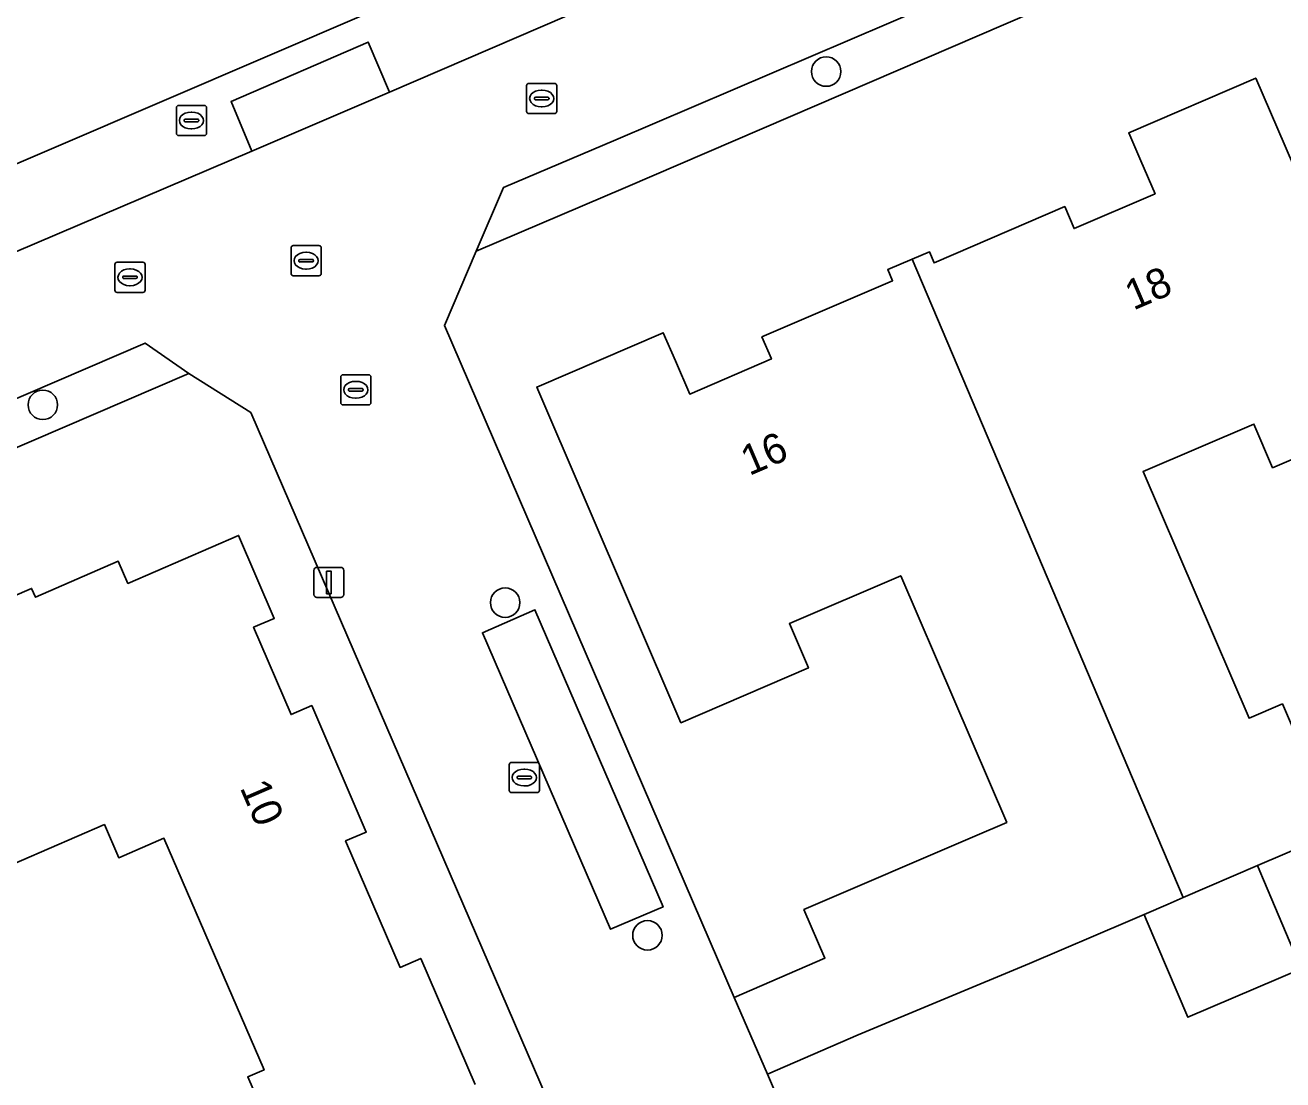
# Model space of a CAD drawing. Extents: x 157767 to 159172, y 387839 to 389425.
# Drawn here: x 158126.83 to 158168.55, y 388760.66 to 388795.64 of the extents above; entities that cross this region are included whole.
import ezdxf

# ---------------------------------------------------------------- set-up
doc = ezdxf.new("R2010")
doc.units = 0
for name, color, linetype in [('IMGEO_Boom', 7, 'Continuous'), ('IMGEO_Brandkraan', 7, 'Continuous'), ('IMGEO_Erf', 7, 'Continuous'), ('IMGEO_Kolk', 7, 'Continuous'), ('IMGEO_Lichtmast', 7, 'Continuous'), ('IMGEO_Pand', 7, 'Continuous'), ('IMGEO_Pand_nummerreeks', 7, 'Continuous'), ('IMGEO_Parkeervlak_open', 7, 'Continuous'), ('IMGEO_Rijbaan_lokaal_open', 7, 'Continuous'), ('IMGEO_Rioolput', 7, 'Continuous'), ('IMGEO_Voetpad_open', 7, 'Continuous')]:
    doc.layers.add(name, color=color, linetype=linetype)

msp = doc.modelspace()

# ---------------------------------------------------------------- linework, layer by layer
at = {"layer": 'IMGEO_Boom'}
for centre in [(158153.405, 388794.103), (158127.417, 388783.049), (158142.755, 388776.488), (158147.475, 388765.452)]:
    msp.add_circle(centre, 0.489, dxfattribs=at)
at = {"layer": 'IMGEO_Brandkraan'}
for p, q in [((158131.848, 388792.054), (158131.848, 388792.906)), ((158131.923, 388792.98), (158132.775, 388792.98)), ((158132.336, 388792.76), (158132.361, 388792.76)), ((158132.849, 388792.906), (158132.849, 388792.054)), ((158132.107, 388792.474), (158132.107, 388792.486)), ((158132.545, 388792.437), (158132.147, 388792.437)), ((158132.15, 388792.523), (158132.548, 388792.523)), ((158132.591, 388792.486), (158132.591, 388792.474)), ((158132.775, 388791.98), (158131.923, 388791.98)), ((158132.359, 388792.2), (158132.334, 388792.2))]:
    msp.add_line(p, q, dxfattribs=at)
for points in [[(158131.848, 388792.054), (158131.848, 388792.906)], [(158131.923, 388792.98), (158132.775, 388792.98)], [(158132.849, 388792.906), (158132.849, 388792.054)], [(158132.775, 388791.98), (158131.923, 388791.98)]]:
    msp.add_lwpolyline(points, dxfattribs=at)
for centre, radius, start, end in [((158131.925, 388792.904), 0.0765, 91.552, 178.448), ((158131.925, 388792.904), 0.0765, 91.552, 178.448), ((158132.773, 388792.904), 0.0765, 1.552, 88.448), ((158132.773, 388792.904), 0.0765, 1.552, 88.448), ((158132.147, 388792.483), 0.0403, 85.8775, 175.7526), ((158132.144, 388792.473), 0.0366, 178.938, 274.7102), ((158132.548, 388792.48), 0.043, 264.8664, 352.4533), ((158132.552, 388792.485), 0.0386, 1.7309, 96.639), ((158131.925, 388792.056), 0.0765, 181.552, 268.448), ((158131.925, 388792.056), 0.0765, 181.552, 268.448), ((158132.773, 388792.056), 0.0765, 271.552, 358.448), ((158132.773, 388792.056), 0.0765, 271.552, 358.448)]:
    msp.add_arc(centre, radius, start, end, dxfattribs=at)
for centre, major_axis, ratio, start_param, end_param in [((158132.335, 388792.48), (-0.387, 0.002), 0.722429, 4.712389, 7.853982), ((158132.36, 388792.48), (-0.39, 0.002), 0.717154, 1.570796, 4.712389)]:
    msp.add_ellipse(centre, major_axis=major_axis, ratio=ratio, start_param=start_param, end_param=end_param, dxfattribs=at)
at = {"layer": 'IMGEO_Erf'}
for points in [[(158089.846, 388837.076), (158089.41, 388836.039), (158086.884, 388830.077), (158084.94, 388825.383), (158082.965, 388820.428), (158081.065, 388815.496), (158080.476, 388813.945), (158079.161, 388810.597), (158077.124, 388804.963), (158075.44, 388800.18), (158073.73, 388794.988), (158072.155, 388790.113), (158071.511, 388787.861), (158072.557, 388785.494), (158096.685, 388778.239), (158159.023, 388804.985), (158161.367, 388806.591), (158183.864, 388823.28), (158184.29, 388826.082), (158183.48, 388827.171), (158150.204, 388871.916)], [(158163.892, 388797.643), (158146.746, 388790.258), (158141.792, 388788.146), (158140.738, 388785.682), (158150.351, 388763.396), (158153.362, 388764.7), (158152.666, 388766.307), (158158.336, 388768.745), (158159.394, 388769.2), (158155.877, 388777.38), (158152.183, 388775.793), (158152.815, 388774.323), (158148.588, 388772.506), (158143.804, 388783.637), (158148.002, 388785.442), (158148.403, 388784.509), (158148.877, 388783.405), (158151.587, 388784.57), (158151.272, 388785.304), (158155.606, 388787.167), (158155.448, 388787.535), (158156.257, 388787.882), (158156.827, 388788.127), (158156.985, 388787.759), (158161.32, 388789.623), (158161.631, 388788.897), (158164.313, 388790.05), (158163.844, 388791.141), (158163.443, 388792.074), (158167.657, 388793.885), (158169.632, 388789.292)], [(158156.474, 388731.409), (158148.476, 388750), (158147.334, 388752.654), (158134.314, 388782.791), (158132.266, 388784.089), (158097.205, 388769.015), (158070.254, 388777.047), (158067.999, 388776.006)], [(158172.434, 388782.773), (158168.215, 388780.961), (158167.592, 388782.413), (158163.916, 388780.834), (158167.434, 388772.654), (158168.537, 388773.128), (158170.355, 388768.901), (158167.709, 388767.764), (158167.787, 388767.578), (158167.907, 388767.297), (158169.164, 388764.337), (158165.399, 388762.738), (158164.022, 388765.978), (158163.95, 388766.148), (158163.406, 388765.914), (158160.153, 388764.516), (158154.467, 388762.149), (158151.457, 388760.844), (158153.258, 388756.655)], [(158125.676, 388776.368), (158127.043, 388776.961), (158127.17, 388776.668), (158129.923, 388777.86), (158130.241, 388777.127), (158133.91, 388778.716), (158135.096, 388775.965), (158134.408, 388775.669), (158135.654, 388772.776), (158136.342, 388773.072), (158138.148, 388768.88), (158137.461, 388768.583), (158139.269, 388764.39), (158139.953, 388764.685), (158141.755, 388760.508)], [(158137.304, 388753.618), (158134.219, 388760.754), (158134.76, 388760.988), (158131.438, 388768.674), (158129.935, 388768.024), (158129.459, 388769.127), (158125.779, 388767.536)]]:
    msp.add_lwpolyline(points, dxfattribs=at)
at = {"layer": 'IMGEO_Kolk'}
for p, q in [((158143.467, 388792.784), (158143.467, 388793.636)), ((158143.542, 388793.71), (158144.394, 388793.71)), ((158144.468, 388793.636), (158144.468, 388792.784)), ((158143.726, 388793.204), (158143.726, 388793.216)), ((158144.164, 388793.167), (158143.766, 388793.167)), ((158143.769, 388793.253), (158144.167, 388793.253)), ((158143.955, 388793.49), (158143.98, 388793.49)), ((158144.21, 388793.216), (158144.21, 388793.204)), ((158144.394, 388792.71), (158143.542, 388792.71)), ((158143.978, 388792.93), (158143.953, 388792.93)), ((158129.81, 388786.853), (158129.81, 388787.705)), ((158129.885, 388787.779), (158130.737, 388787.779)), ((158130.811, 388787.705), (158130.811, 388786.853)), ((158130.069, 388787.273), (158130.069, 388787.285)), ((158130.112, 388787.322), (158130.51, 388787.322)), ((158130.298, 388787.559), (158130.323, 388787.559)), ((158130.553, 388787.285), (158130.553, 388787.273)), ((158130.507, 388787.236), (158130.109, 388787.236)), ((158130.321, 388786.999), (158130.296, 388786.999)), ((158130.737, 388786.779), (158129.885, 388786.779)), ((158137.3, 388783.122), (158137.3, 388783.974)), ((158137.375, 388784.048), (158138.227, 388784.048)), ((158138.301, 388783.974), (158138.301, 388783.122)), ((158137.559, 388783.542), (158137.559, 388783.554)), ((158137.997, 388783.505), (158137.599, 388783.505)), ((158137.602, 388783.591), (158138, 388783.591)), ((158137.788, 388783.828), (158137.813, 388783.828)), ((158138.043, 388783.554), (158138.043, 388783.542)), ((158137.811, 388783.268), (158137.786, 388783.268)), ((158138.227, 388783.048), (158137.375, 388783.048)), ((158142.891, 388770.261), (158142.891, 388771.113)), ((158142.966, 388771.187), (158143.818, 388771.187)), ((158143.892, 388771.113), (158143.892, 388770.261)), ((158143.15, 388770.681), (158143.15, 388770.693)), ((158143.588, 388770.644), (158143.19, 388770.644)), ((158143.193, 388770.73), (158143.591, 388770.73)), ((158143.379, 388770.967), (158143.404, 388770.967)), ((158143.634, 388770.693), (158143.634, 388770.681)), ((158143.818, 388770.187), (158142.966, 388770.187)), ((158143.402, 388770.407), (158143.377, 388770.407))]:
    msp.add_line(p, q, dxfattribs=at)
for points in [[(158143.467, 388792.784), (158143.467, 388793.636)], [(158143.542, 388793.71), (158144.394, 388793.71)], [(158144.468, 388793.636), (158144.468, 388792.784)], [(158144.394, 388792.71), (158143.542, 388792.71)], [(158129.81, 388786.853), (158129.81, 388787.705)], [(158129.885, 388787.779), (158130.737, 388787.779)], [(158130.811, 388787.705), (158130.811, 388786.853)], [(158130.737, 388786.779), (158129.885, 388786.779)], [(158137.3, 388783.122), (158137.3, 388783.974)], [(158137.375, 388784.048), (158138.227, 388784.048)], [(158138.301, 388783.974), (158138.301, 388783.122)], [(158138.227, 388783.048), (158137.375, 388783.048)], [(158142.891, 388770.261), (158142.891, 388771.113)], [(158142.966, 388771.187), (158143.818, 388771.187)], [(158143.892, 388771.113), (158143.892, 388770.261)], [(158143.818, 388770.187), (158142.966, 388770.187)]]:
    msp.add_lwpolyline(points, dxfattribs=at)
for centre, radius, start, end in [((158143.544, 388793.634), 0.0765, 91.552, 178.448), ((158143.544, 388793.634), 0.0765, 91.552, 178.448), ((158144.392, 388793.634), 0.0765, 1.552, 88.448), ((158144.392, 388793.634), 0.0765, 1.552, 88.448), ((158143.766, 388793.213), 0.0403, 85.8775, 175.7526), ((158143.763, 388793.203), 0.0366, 178.938, 274.7102), ((158144.167, 388793.21), 0.043, 264.8664, 352.4533), ((158144.171, 388793.215), 0.0386, 1.7309, 96.639), ((158143.544, 388792.786), 0.0765, 181.552, 268.448), ((158143.544, 388792.786), 0.0765, 181.552, 268.448), ((158144.392, 388792.786), 0.0765, 271.552, 358.448), ((158144.392, 388792.786), 0.0765, 271.552, 358.448), ((158129.887, 388787.703), 0.0765, 91.552, 178.448), ((158129.887, 388787.703), 0.0765, 91.552, 178.448), ((158130.735, 388787.703), 0.0765, 1.552, 88.448), ((158130.735, 388787.703), 0.0765, 1.552, 88.448), ((158130.109, 388787.282), 0.0403, 85.8775, 175.7526), ((158130.106, 388787.272), 0.0366, 178.938, 274.7102), ((158130.51, 388787.279), 0.043, 264.8664, 352.4533), ((158130.514, 388787.284), 0.0386, 1.7309, 96.639), ((158129.887, 388786.855), 0.0765, 181.552, 268.448), ((158129.887, 388786.855), 0.0765, 181.552, 268.448), ((158130.735, 388786.855), 0.0765, 271.552, 358.448), ((158130.735, 388786.855), 0.0765, 271.552, 358.448), ((158137.377, 388783.972), 0.0765, 91.552, 178.448), ((158137.377, 388783.972), 0.0765, 91.552, 178.448), ((158138.225, 388783.972), 0.0765, 1.552, 88.448), ((158138.225, 388783.972), 0.0765, 1.552, 88.448), ((158137.599, 388783.551), 0.0403, 85.8775, 175.7526), ((158137.596, 388783.541), 0.0366, 178.938, 274.7102), ((158138, 388783.548), 0.043, 264.8664, 352.4533), ((158138.004, 388783.553), 0.0386, 1.7309, 96.639), ((158137.377, 388783.124), 0.0765, 181.552, 268.448), ((158137.377, 388783.124), 0.0765, 181.552, 268.448), ((158138.225, 388783.124), 0.0765, 271.552, 358.448), ((158138.225, 388783.124), 0.0765, 271.552, 358.448), ((158142.968, 388771.111), 0.0765, 91.552, 178.448), ((158142.968, 388771.111), 0.0765, 91.552, 178.448), ((158143.816, 388771.111), 0.0765, 1.552, 88.448), ((158143.816, 388771.111), 0.0765, 1.552, 88.448), ((158143.19, 388770.69), 0.0403, 85.8775, 175.7526), ((158143.187, 388770.68), 0.0366, 178.938, 274.7102), ((158143.591, 388770.687), 0.043, 264.8664, 352.4533), ((158143.595, 388770.692), 0.0386, 1.7309, 96.639), ((158142.968, 388770.263), 0.0765, 181.552, 268.448), ((158142.968, 388770.263), 0.0765, 181.552, 268.448), ((158143.816, 388770.263), 0.0765, 271.552, 358.448), ((158143.816, 388770.263), 0.0765, 271.552, 358.448)]:
    msp.add_arc(centre, radius, start, end, dxfattribs=at)
for centre, major_axis, ratio, start_param, end_param in [((158143.954, 388793.21), (-0.387, 0.002), 0.722429, 4.712389, 7.853982), ((158143.979, 388793.21), (-0.39, 0.002), 0.717154, 1.570796, 4.712389), ((158130.297, 388787.279), (-0.387, 0.002), 0.722429, 4.712389, 7.853982), ((158130.322, 388787.279), (-0.39, 0.002), 0.717154, 1.570796, 4.712389), ((158137.787, 388783.548), (-0.387, 0.002), 0.722429, 4.712389, 7.853982), ((158137.812, 388783.548), (-0.39, 0.002), 0.717154, 1.570796, 4.712389), ((158143.378, 388770.687), (-0.387, 0.002), 0.722429, 4.712389, 7.853982), ((158143.403, 388770.687), (-0.39, 0.002), 0.717154, 1.570796, 4.712389)]:
    msp.add_ellipse(centre, major_axis=major_axis, ratio=ratio, start_param=start_param, end_param=end_param, dxfattribs=at)
at = {"layer": 'IMGEO_Lichtmast'}
for p, q in [((158136.512, 388777.658), (158137.302, 388777.658)), ((158137.302, 388777.658), (158136.512, 388777.658)), ((158136.412, 388776.758), (158136.412, 388777.558)), ((158136.412, 388777.558), (158136.412, 388776.758)), ((158137.402, 388777.558), (158137.402, 388776.758)), ((158137.402, 388776.758), (158137.402, 388777.558)), ((158137.302, 388776.658), (158136.512, 388776.658)), ((158136.512, 388776.658), (158137.302, 388776.658))]:
    msp.add_line(p, q, dxfattribs=at)
msp.add_lwpolyline([(158136.832, 388777.533), (158136.982, 388777.533), (158136.982, 388776.783), (158136.832, 388776.783), (158136.832, 388777.533)], dxfattribs=at)
for centre, start, end in [((158136.512, 388777.558), 90, 180), ((158136.512, 388777.558), 90, 180), ((158137.302, 388777.558), 0, 90), ((158137.302, 388777.558), 360, 90), ((158136.512, 388776.758), 180, 270), ((158136.512, 388776.758), 180, 270), ((158137.302, 388776.758), 270, 0), ((158137.302, 388776.758), 270, 0)]:
    msp.add_arc(centre, 0.1, start, end, dxfattribs=at)
at = {"layer": 'IMGEO_Pand'}
for points in [[(158169.632, 388789.292), (158167.657, 388793.885), (158163.443, 388792.074), (158163.844, 388791.141), (158164.313, 388790.05), (158161.631, 388788.897), (158161.32, 388789.623), (158156.985, 388787.759), (158156.827, 388788.127), (158156.257, 388787.882), (158165.252, 388766.708), (158167.709, 388767.764), (158170.355, 388768.901), (158168.537, 388773.128), (158167.434, 388772.654), (158163.916, 388780.834), (158167.592, 388782.413), (158168.215, 388780.961), (158172.434, 388782.773)], [(158156.257, 388787.882), (158155.448, 388787.535), (158155.606, 388787.167), (158151.272, 388785.304), (158151.587, 388784.57), (158148.877, 388783.405), (158148.403, 388784.509), (158148.002, 388785.442), (158143.804, 388783.637), (158148.588, 388772.506), (158152.815, 388774.323), (158152.183, 388775.793), (158155.877, 388777.38), (158159.394, 388769.2), (158158.336, 388768.745), (158152.666, 388766.307), (158153.362, 388764.7), (158150.351, 388763.396), (158151.457, 388760.844), (158154.467, 388762.149), (158160.153, 388764.516), (158163.406, 388765.914), (158163.95, 388766.148), (158164.747, 388766.491), (158165.252, 388766.708)], [(158167.709, 388767.764), (158165.252, 388766.708), (158164.747, 388766.491), (158163.95, 388766.148), (158164.022, 388765.978), (158165.399, 388762.738), (158169.164, 388764.337), (158167.907, 388767.297), (158167.787, 388767.578)]]:
    msp.add_lwpolyline(points, close=True, dxfattribs=at)
for points in [[(158141.755, 388760.508), (158139.953, 388764.685), (158139.269, 388764.39), (158137.461, 388768.583), (158138.148, 388768.88), (158136.342, 388773.072), (158135.654, 388772.776), (158134.408, 388775.669), (158135.096, 388775.965), (158133.91, 388778.716), (158130.241, 388777.127), (158129.923, 388777.86), (158127.17, 388776.668), (158127.043, 388776.961), (158125.676, 388776.368)], [(158125.779, 388767.536), (158129.459, 388769.127), (158129.935, 388768.024), (158131.438, 388768.674), (158134.76, 388760.988), (158134.219, 388760.754), (158137.304, 388753.618)]]:
    msp.add_lwpolyline(points, dxfattribs=at)
at = {"layer": 'IMGEO_Parkeervlak_open'}
for points in [[(158134.35, 388791.467), (158138.917, 388793.421), (158138.212, 388795.082), (158133.661, 388793.113)], [(158146.255, 388765.655), (158147.995, 388766.393), (158143.745, 388776.252), (158142.001, 388775.49)]]:
    msp.add_lwpolyline(points, close=True, dxfattribs=at)
at = {"layer": 'IMGEO_Rijbaan_lokaal_open'}
for points in [[(158159.71, 388741.661), (158158, 388745.6), (158153.258, 388756.655), (158151.457, 388760.844), (158150.351, 388763.396), (158140.738, 388785.682), (158141.792, 388788.146), (158142.695, 388790.255), (158146.431, 388791.842), (158163.248, 388799.033), (158188.187, 388817.592), (158186.893, 388819.339), (158185.476, 388821.253), (158180.415, 388817.471), (158176.475, 388814.546), (158168.424, 388808.555), (158164.54, 388805.671), (158160.439, 388802.656), (158154.49, 388800.108), (158149.891, 388798.147), (158138.917, 388793.421), (158134.35, 388791.467), (158122.856, 388786.566)], [(158097.692, 388770.854), (158130.812, 388785.098), (158132.266, 388784.089), (158134.314, 388782.791), (158147.334, 388752.654), (158148.476, 388750), (158156.474, 388731.409)]]:
    msp.add_lwpolyline(points, dxfattribs=at)
msp.add_lwpolyline([(158142.001, 388775.49), (158143.745, 388776.252), (158147.995, 388766.393), (158146.255, 388765.655)], close=True, dxfattribs=at)
at = {"layer": 'IMGEO_Rioolput'}
for p, q in [((158135.652, 388787.404), (158135.652, 388788.256)), ((158135.727, 388788.33), (158136.579, 388788.33)), ((158136.14, 388788.11), (158136.165, 388788.11)), ((158136.653, 388788.256), (158136.653, 388787.404)), ((158135.911, 388787.824), (158135.911, 388787.836)), ((158136.349, 388787.787), (158135.951, 388787.787)), ((158135.954, 388787.873), (158136.352, 388787.873)), ((158136.395, 388787.836), (158136.395, 388787.824)), ((158136.579, 388787.33), (158135.727, 388787.33)), ((158136.163, 388787.55), (158136.138, 388787.55))]:
    msp.add_line(p, q, dxfattribs=at)
for points in [[(158135.652, 388787.404), (158135.652, 388788.256)], [(158135.727, 388788.33), (158136.579, 388788.33)], [(158136.653, 388788.256), (158136.653, 388787.404)], [(158136.579, 388787.33), (158135.727, 388787.33)]]:
    msp.add_lwpolyline(points, dxfattribs=at)
for centre, radius, start, end in [((158135.729, 388788.254), 0.0765, 91.552, 178.448), ((158135.729, 388788.254), 0.0765, 91.552, 178.448), ((158136.577, 388788.254), 0.0765, 1.552, 88.448), ((158136.577, 388788.254), 0.0765, 1.552, 88.448), ((158135.951, 388787.833), 0.0403, 85.8775, 175.7526), ((158135.948, 388787.823), 0.0366, 178.938, 274.7102), ((158136.352, 388787.83), 0.043, 264.8664, 352.4533), ((158136.356, 388787.835), 0.0386, 1.7309, 96.639), ((158135.729, 388787.406), 0.0765, 181.552, 268.448), ((158135.729, 388787.406), 0.0765, 181.552, 268.448), ((158136.577, 388787.406), 0.0765, 271.552, 358.448), ((158136.577, 388787.406), 0.0765, 271.552, 358.448)]:
    msp.add_arc(centre, radius, start, end, dxfattribs=at)
for centre, major_axis, ratio, start_param, end_param in [((158136.139, 388787.83), (-0.387, 0.002), 0.722429, 4.712389, 7.853982), ((158136.164, 388787.83), (-0.39, 0.002), 0.717154, 1.570796, 4.712389)]:
    msp.add_ellipse(centre, major_axis=major_axis, ratio=ratio, start_param=start_param, end_param=end_param, dxfattribs=at)
at = {"layer": 'IMGEO_Voetpad_open'}
msp.add_lwpolyline([(158122.856, 388786.566), (158134.35, 388791.467), (158133.661, 388793.113), (158138.212, 388795.082), (158138.917, 388793.421), (158149.891, 388798.147), (158149.189, 388799.807), (158153.767, 388801.774), (158154.49, 388800.108), (158160.439, 388802.656), (158164.54, 388805.671), (158163.485, 388807.144), (158167.386, 388810.027), (158168.424, 388808.555), (158176.475, 388814.546), (158175.399, 388815.997), (158179.336, 388818.887), (158180.415, 388817.471), (158185.476, 388821.253), (158183.864, 388823.28), (158161.367, 388806.591), (158159.023, 388804.985), (158096.685, 388778.239)], dxfattribs=at)
for points in [[(158163.892, 388797.643), (158189.191, 388816.451), (158188.187, 388817.592), (158163.248, 388799.033), (158146.431, 388791.842), (158142.695, 388790.255), (158141.792, 388788.146), (158146.746, 388790.258)], [(158132.266, 388784.089), (158130.812, 388785.098), (158097.692, 388770.854), (158097.152, 388770.606), (158071.312, 388778.281), (158070.254, 388777.047), (158097.205, 388769.015)]]:
    msp.add_lwpolyline(points, close=True, dxfattribs=at)

# ---------------------------------------------------------------- texts
at = {"layer": 'IMGEO_Pand_nummerreeks'}
for s, rotation, p in [('18', 23.2621, (158163.594, 388786.171)), ('16', 23.2621, (158150.851, 388780.684)), ('10', 293.3074, (158133.943, 388770.352))]:
    msp.add_text(s, height=1, rotation=rotation, dxfattribs=at).set_placement(p)

doc.saveas('drawing.dxf')
